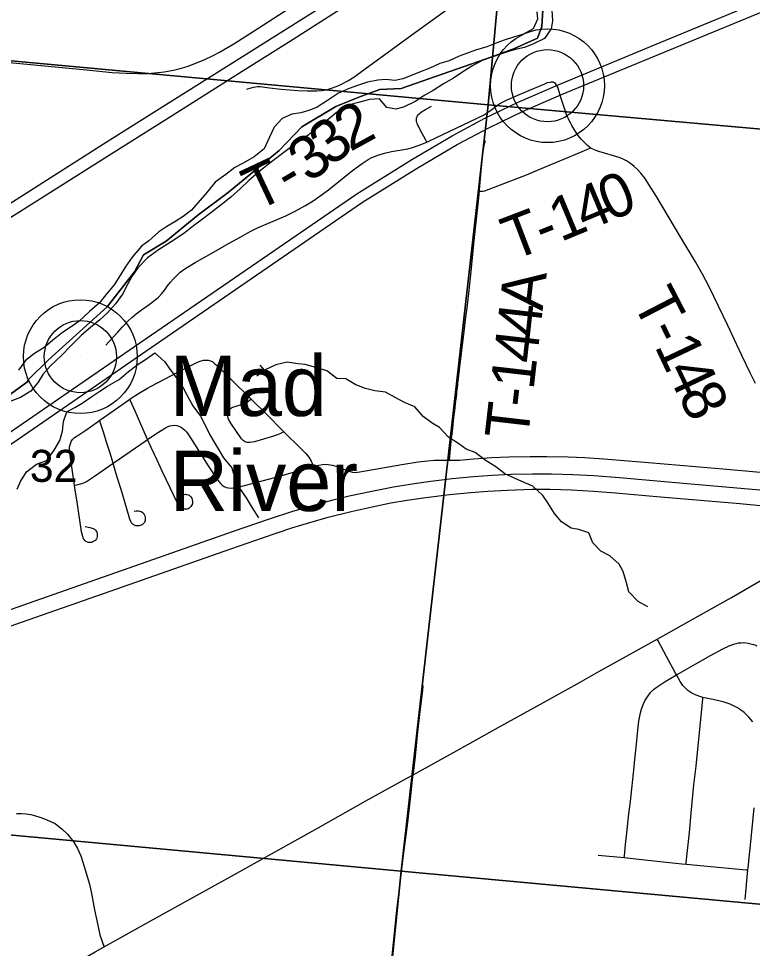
# Model space of a CAD drawing. Extents: x 831 to 1552, y 430 to 870.
# Drawn here: x 1333.77 to 1352.96, y 678.59 to 702.9 of the extents above; entities that cross this region are included whole.
import ezdxf

# ---------------------------------------------------------------- set-up
doc = ezdxf.new("R2010")
doc.units = 0
for name, color, linetype in [('GM_X_Corporation', 7, 'Continuous'), ('GM_X_County_Road', 7, 'Continuous'), ('GM_X_Interstate_Route', 7, 'Continuous'), ('GM_X_Major_River', 7, 'Continuous'), ('GM_X_Minor_River', 7, 'Continuous'), ('GM_X_Rail_Line', 7, 'Continuous'), ('GM_X_Section_Text', 7, 'Continuous'), ('GM_X_State_Route', 7, 'Continuous'), ('GM_X_Township_Road', 7, 'Continuous'), ('GM_X_Township_Road_Text', 7, 'Continuous'), ('GM_X_Unincorporated', 7, 'Continuous'), ('GM_X_Unincorporated_Location', 7, 'Continuous'), ('GM_X_Unincorporated_Text', 7, 'Continuous')]:
    doc.layers.add(name, color=color, linetype=linetype)

msp = doc.modelspace()

# ---------------------------------------------------------------- linework, layer by layer
at = {"layer": 'GM_X_Corporation'}
for points in [[(1327.468, 722.912), (1347.89, 720.702), (1346.049, 700.645), (1325.539, 702.531)], [(1347.89, 720.702), (1366.951, 719.126), (1365.244, 698.931), (1346.049, 700.645)], [(1325.539, 702.531), (1346.049, 700.645), (1343.776, 680.603), (1323.531, 682.478)], [(1346.049, 700.645), (1365.244, 698.931), (1363.462, 678.79), (1343.776, 680.603)], [(1323.531, 682.478), (1343.776, 680.603), (1341.746, 660.547), (1321.979, 662.503), (1321.541, 662.548)], [(1343.776, 680.603), (1363.462, 678.79), (1361.646, 658.883), (1342.018, 660.52), (1341.746, 660.547)]]:
    msp.add_lwpolyline(points, close=True, dxfattribs=at)
for points in [[(1347.533, 704.01), (1347.45, 702.69), (1347.341, 702.388), (1346.735, 702.112), (1346.146, 701.901), (1343.779, 701.073), (1343.216, 701.043), (1342.713, 700.865), (1342.062, 700.599), (1341.175, 700.067), (1340.583, 699.445), (1339.252, 698.351), (1338.453, 697.76), (1337.624, 697.079), (1337.032, 696.725), (1336.796, 696.281), (1336.086, 695.363), (1334.547, 693.974), (1334.014, 693.441), (1334.014, 693.412), (1333.334, 692.909)], [(1333.334, 692.909), (1334.014, 693.412), (1334.014, 693.441), (1334.547, 693.974), (1336.086, 695.363), (1336.796, 696.281), (1337.032, 696.725), (1337.624, 697.079), (1338.453, 697.76), (1339.252, 698.351), (1340.583, 699.445), (1341.175, 700.067), (1342.062, 700.599), (1342.713, 700.865), (1343.216, 701.043), (1343.779, 701.073), (1346.146, 701.901), (1346.735, 702.112), (1347.341, 702.388), (1347.45, 702.69), (1347.533, 704.01)]]:
    msp.add_lwpolyline(points, dxfattribs=at)
at = {"layer": 'GM_X_County_Road'}
for points in [[(1339.741, 701.05), (1339.853, 701.09), (1339.911, 701.105), (1339.969, 701.116), (1340.028, 701.121), (1340.087, 701.121), (1340.146, 701.117), (1340.328, 701.088), (1340.639, 701.052), (1341.072, 701.016), (1341.32, 701.006), (1341.567, 701.01), (1341.689, 701.019), (1341.81, 701.039), (1341.928, 701.072), (1342.103, 701.134), (1342.216, 701.183), (1342.378, 701.271), (1342.534, 701.37), (1342.837, 701.586), (1344.242, 702.614), (1346.358, 704.142)], [(1333.431, 701.759), (1334.174, 701.687), (1335.541, 701.56), (1336.215, 701.491), (1336.586, 701.467), (1336.896, 701.46), (1337.143, 701.465), (1337.328, 701.478), (1337.574, 701.508), (1337.818, 701.553), (1337.998, 701.595), (1338.176, 701.647), (1338.408, 701.732), (1338.637, 701.827), (1338.861, 701.933), (1339.025, 702.019), (1339.399, 702.241), (1340.029, 702.639), (1340.863, 703.18)], [(1350.474, 686.674), (1350.626, 686.759), (1351.385, 687.184), (1352.413, 687.764), (1353.169, 688.195), (1354.196, 688.777), (1354.905, 689.182)], [(1344.092, 683.128), (1345.304, 683.797), (1346.314, 684.361), (1347.422, 684.975), (1348.453, 685.551), (1348.942, 685.823), (1350.474, 686.674)], [(1331.36, 675.855), (1332.212, 676.385), (1332.741, 676.712), (1333.326, 677.065), (1333.915, 677.412), (1334.449, 677.729), (1335.436, 678.305), (1335.775, 678.495), (1337.039, 679.206), (1338.832, 680.197), (1339.319, 680.469), (1341.602, 681.739), (1342.853, 682.441), (1344.04, 683.099), (1344.092, 683.128)]]:
    msp.add_lwpolyline(points, dxfattribs=at)
at = {"layer": 'GM_X_Interstate_Route'}
for points in [[(1331.945, 686.879), (1334.348, 687.724), (1336.811, 688.586), (1339.389, 689.495), (1340.328, 689.819), (1340.919, 690.009), (1341.454, 690.169), (1341.993, 690.315), (1342.415, 690.418), (1342.961, 690.537), (1343.571, 690.654), (1344.06, 690.737), (1344.552, 690.807), (1345.107, 690.872), (1345.663, 690.924), (1346.158, 690.96), (1346.654, 690.983), (1347.213, 690.996), (1347.709, 690.995), (1348.268, 690.98), (1348.81, 690.952), (1349.484, 690.9), (1351.054, 690.763), (1355.364, 690.381)], [(1331.762, 686.388), (1333.874, 687.124), (1336.335, 687.989), (1339.148, 688.976), (1340.145, 689.324), (1340.912, 689.579), (1341.387, 689.725), (1341.866, 689.859), (1342.469, 690.011), (1343.015, 690.135), (1343.502, 690.234), (1343.931, 690.309), (1344.423, 690.379), (1345.041, 690.452), (1345.597, 690.507), (1346.045, 690.543), (1346.558, 690.571), (1347.19, 690.591), (1347.671, 690.591), (1348.231, 690.575), (1348.804, 690.543), (1349.385, 690.495), (1350.561, 690.395), (1352.541, 690.224), (1355.298, 689.97)]]:
    msp.add_lwpolyline(points, dxfattribs=at)
at = {"layer": 'GM_X_Major_River'}
for points in [[(1347.715, 703.116), (1347.732, 702.842), (1347.696, 702.629)], [(1347.326, 703.071), (1347.337, 702.881), (1347.225, 702.632), (1346.978, 702.493), (1346.71, 702.415)], [(1347.696, 702.629), (1347.523, 702.375), (1347.239, 702.236), (1347.001, 702.143), (1346.802, 702.101), (1346.611, 702.045), (1346.396, 701.981), (1346.12, 701.881), (1345.89, 701.802), (1345.621, 701.656), (1345.366, 701.486), (1345.142, 701.339), (1344.88, 701.193), (1344.61, 701.016), (1344.394, 700.892), (1344.139, 700.73), (1343.839, 700.584), (1343.633, 700.528), (1343.398, 700.571), (1343.205, 700.804), (1342.946, 700.779), (1342.655, 700.702), (1342.388, 700.639), (1342.11, 700.463), (1341.87, 700.27), (1341.583, 700.041), (1341.367, 699.871), (1341.142, 699.708), (1340.949, 699.576), (1340.632, 699.347), (1340.307, 699.095), (1340.044, 698.881), (1339.788, 698.666), (1339.562, 698.45), (1339.321, 698.227), (1339.066, 698.027), (1338.795, 697.82), (1338.54, 697.628), (1338.339, 697.481), (1338.122, 697.303), (1337.828, 697.104), (1337.427, 696.854), (1337.141, 696.64), (1336.884, 696.38), (1336.727, 696.155), (1336.623, 695.959), (1336.488, 695.696), (1336.307, 695.441), (1336.089, 695.195), (1335.895, 695.025), (1335.647, 694.817), (1335.414, 694.617), (1335.142, 694.349), (1334.892, 694.088), (1334.605, 693.821), (1334.402, 693.59), (1334.284, 693.395), (1334.088, 693.156), (1333.818, 692.994), (1333.565, 692.893)], [(1346.71, 702.415), (1346.465, 702.337), (1346.273, 702.265), (1346.012, 702.157), (1345.721, 702.072), (1345.484, 701.986), (1345.292, 701.914), (1345.03, 701.79), (1344.786, 701.727), (1344.524, 701.604), (1344.256, 701.496), (1344.064, 701.416), (1343.818, 701.323), (1343.619, 701.281), (1343.361, 701.302), (1343.163, 701.284), (1342.896, 701.237), (1342.635, 701.151), (1342.413, 701.072), (1342.136, 700.949), (1341.851, 700.758), (1341.58, 700.581), (1341.388, 700.502), (1341.151, 700.438), (1340.914, 700.398), (1340.661, 700.289), (1340.45, 700.058), (1340.33, 699.795), (1340.194, 699.493), (1339.931, 699.286), (1339.638, 699.118), (1339.422, 699.001), (1339.19, 698.823), (1338.912, 698.624), (1338.693, 698.355), (1338.521, 698.154), (1338.287, 697.885), (1338.07, 697.722), (1337.854, 697.583), (1337.646, 697.458), (1337.437, 697.326), (1337.174, 697.088), (1336.98, 696.948), (1336.738, 696.664), (1336.557, 696.402), (1336.431, 696.199), (1336.265, 695.937), (1336.054, 695.675), (1335.882, 695.466), (1335.626, 695.236), (1335.354, 694.983), (1335.114, 694.821), (1334.921, 694.689), (1334.658, 694.482), (1334.433, 694.296), (1334.186, 694.142), (1333.946, 693.957), (1333.766, 693.71)]]:
    msp.add_lwpolyline(points, dxfattribs=at)
at = {"layer": 'GM_X_Minor_River'}
for points in [[(1333.728, 690.597), (1333.814, 690.793), (1333.977, 691.05), (1334.237, 691.251), (1334.504, 691.347), (1334.698, 691.61), (1334.845, 691.867), (1334.916, 692.109), (1334.942, 692.367), (1335.029, 692.616), (1335.236, 692.728), (1335.427, 692.839), (1335.687, 693.019), (1335.894, 693.153), (1336.093, 693.287), (1336.399, 693.466), (1336.645, 693.668), (1336.898, 693.862), (1337.09, 693.989), (1337.335, 694.161), (1337.59, 693.922), (1337.725, 693.731), (1337.889, 693.516), (1338.076, 693.24), (1338.18, 693.042), (1338.328, 692.774), (1338.522, 692.506), (1338.671, 692.216), (1338.767, 692.017), (1338.886, 691.826), (1339.013, 691.604), (1339.132, 691.413), (1339.349, 691.152), (1339.422, 690.885), (1339.548, 690.618), (1339.719, 690.365), (1339.876, 690.105), (1340.047, 689.845)], [(1350.229, 687.515), (1349.972, 687.655), (1349.732, 687.908), (1349.667, 688.144), (1349.579, 688.441), (1349.475, 688.632), (1349.235, 688.848), (1349.001, 688.972), (1348.791, 689.195), (1348.68, 689.454), (1348.423, 689.541), (1348.218, 689.574), (1347.969, 689.736), (1347.782, 689.958), (1347.611, 690.241), (1347.477, 690.433), (1347.221, 690.671), (1347.01, 690.757), (1346.76, 690.874), (1346.488, 690.999), (1346.247, 691.176), (1345.976, 691.354), (1345.713, 691.555), (1345.478, 691.641), (1345.282, 691.78), (1345.011, 691.958), (1344.779, 692.204), (1344.583, 692.32), (1344.349, 692.497), (1344.132, 692.743), (1343.86, 692.86), (1343.618, 692.992), (1343.369, 693.132), (1343.089, 693.165), (1342.846, 693.229), (1342.589, 693.323), (1342.325, 693.478), (1342.09, 693.489), (1341.827, 693.689), (1341.539, 693.776), (1341.266, 693.855), (1341.069, 693.873), (1340.789, 693.914), (1340.499, 693.842), (1340.239, 693.723), (1340.002, 693.552)], [(1340.206, 693.699), (1340.089, 693.839)]]:
    msp.add_lwpolyline(points, dxfattribs=at)
at = {"layer": 'GM_X_Rail_Line'}
for points in [[(1331.029, 690.356), (1334.139, 692.492), (1336.804, 694.323), (1342.617, 698.318), (1344.051, 699.217), (1345.113, 699.834), (1345.965, 700.291), (1346.839, 700.712), (1347.861, 701.155), (1350.4, 702.208), (1352.984, 703.272), (1355.322, 704.238), (1357.221, 705.009), (1357.803, 705.212), (1358.348, 705.377), (1359.339, 705.66), (1360.057, 705.898), (1360.633, 706.108), (1361.404, 706.431)], [(1324.617, 685.605), (1327.389, 687.515), (1329.015, 688.636), (1331.181, 690.137), (1334.291, 692.272), (1336.956, 694.104), (1342.764, 698.096), (1344.19, 698.989), (1345.244, 699.602), (1346.087, 700.054), (1346.951, 700.47), (1347.965, 700.91), (1350.503, 701.962), (1353.086, 703.026), (1355.423, 703.992), (1360.057, 705.898)]]:
    msp.add_lwpolyline(points, dxfattribs=at)
at = {"layer": 'GM_X_State_Route'}
for points in [[(1333.187, 697.843), (1335.988, 699.621), (1336.934, 700.218), (1339.247, 701.676), (1342.98, 704.025), (1344.137, 704.754), (1345.24, 705.451), (1347.026, 706.576), (1348.077, 707.238), (1349.128, 707.902), (1350.076, 708.496), (1351.915, 709.656), (1352.545, 710.051), (1352.915, 710.283), (1353.297, 710.524), (1353.703, 710.78), (1354.282, 711.144), (1356.61, 712.615), (1357.165, 712.965)], [(1327.572, 693.951), (1327.781, 694.084), (1329.474, 695.148), (1330.997, 696.104), (1332.731, 697.181), (1334.273, 698.15), (1336.026, 699.258), (1337.813, 700.381), (1339.619, 701.524), (1340.853, 702.296), (1342.496, 703.341), (1344.305, 704.48), (1346.259, 705.713), (1348.062, 706.849), (1349.964, 708.043), (1351.69, 709.137), (1352.765, 709.811)]]:
    msp.add_lwpolyline(points, dxfattribs=at)
at = {"layer": 'GM_X_Township_Road'}
for p, q in [((1348.928, 681.028), (1349.611, 680.96)), ((1352.773, 679.862), (1352.842, 680.637))]:
    msp.add_line(p, q, dxfattribs=at)
for points in [[(1344.45, 699.671), (1344.477, 699.682), (1344.7, 699.785), (1345.926, 700.377), (1346.034, 700.44), (1346.089, 700.474), (1346.14, 700.509), (1346.232, 700.591), (1346.333, 700.658), (1346.44, 700.718), (1346.55, 700.773), (1346.89, 700.923), (1347.532, 701.195), (1347.605, 701.223), (1347.677, 701.239), (1347.707, 701.244), (1347.73, 701.244), (1347.749, 701.238)], [(1348.733, 699.516), (1348.697, 699.54), (1348.646, 699.583), (1348.567, 699.658), (1348.482, 699.749), (1348.403, 699.843), (1348.331, 699.942), (1348.237, 700.102), (1348.209, 700.157), (1348.181, 700.217), (1348.153, 700.273), (1348.129, 700.33), (1348.103, 700.388), (1347.96, 700.808), (1347.91, 700.987), (1347.892, 701.046), (1347.87, 701.102), (1347.842, 701.154), (1347.808, 701.201), (1347.786, 701.218), (1347.749, 701.238)], [(1344.45, 699.671), (1344.41, 699.741), (1344.286, 699.957), (1344.216, 700.099), (1344.203, 700.13), (1344.191, 700.16), (1344.18, 700.202), (1344.175, 700.24), (1344.177, 700.291), (1344.185, 700.324), (1344.198, 700.354), (1344.215, 700.378), (1344.243, 700.409), (1344.308, 700.459), (1344.408, 700.522), (1344.572, 700.611)], [(1345.822, 698.39), (1345.825, 698.419), (1345.867, 698.913), (1345.891, 699.171), (1345.909, 699.361), (1345.925, 699.461), (1345.934, 699.528), (1345.956, 699.621), (1345.981, 699.713)], [(1336.049, 694.356), (1336.223, 694.555), (1336.362, 694.702), (1336.483, 694.836), (1336.638, 694.994), (1336.727, 695.081), (1336.84, 695.18), (1336.984, 695.284), (1337.185, 695.423), (1337.335, 695.535), (1337.431, 695.615), (1337.515, 695.709), (1337.591, 695.808), (1337.663, 695.907), (1337.738, 696.004), (1337.818, 696.097), (1337.905, 696.184), (1337.998, 696.264), (1338.146, 696.374), (1338.389, 696.522), (1338.822, 696.767), (1339.276, 697.024), (1339.483, 697.14), (1339.642, 697.226), (1339.828, 697.332), (1340.021, 697.423), (1340.304, 697.546), (1340.761, 697.741), (1340.984, 697.852), (1341.257, 698.001), (1341.469, 698.131), (1341.623, 698.237), (1341.874, 698.421), (1342.505, 698.924), (1342.753, 699.11), (1342.908, 699.212), (1343.009, 699.267), (1343.057, 699.287), (1343.167, 699.329), (1343.34, 699.379), (1343.522, 699.419), (1343.951, 699.496), (1344.072, 699.528), (1344.248, 699.589), (1344.45, 699.671)], [(1345.822, 698.39), (1345.86, 698.39), (1345.909, 698.39), (1345.96, 698.395), (1346.304, 698.523), (1347.057, 698.814), (1347.568, 699.027), (1348.072, 699.24), (1348.447, 699.396), (1348.692, 699.498), (1348.733, 699.516)], [(1353.041, 693.36), (1352.9, 693.637), (1352.683, 694.088), (1352.551, 694.369), (1352.315, 694.876), (1352.077, 695.383), (1351.833, 695.885), (1351.659, 696.213), (1351.475, 696.537), (1351.091, 697.176), (1350.45, 698.243), (1350.256, 698.56), (1350.153, 698.713), (1350.042, 698.859), (1349.96, 698.95), (1349.869, 699.032), (1349.773, 699.109), (1349.671, 699.176), (1349.617, 699.206), (1349.505, 699.254), (1349.329, 699.311), (1349.095, 699.379), (1348.948, 699.425), (1348.875, 699.45), (1348.833, 699.464), (1348.785, 699.483), (1348.748, 699.505), (1348.733, 699.516)], [(1345.04, 691.356), (1345.064, 691.657), (1345.093, 691.922), (1345.114, 692.105), (1345.136, 692.288), (1345.156, 692.466), (1345.178, 692.649), (1345.208, 692.891), (1345.22, 693.009), (1345.228, 693.066), (1345.234, 693.128), (1345.241, 693.188), (1345.254, 693.31), (1345.261, 693.37), (1345.273, 693.492), (1345.308, 693.797), (1345.427, 694.721), (1345.469, 695.092), (1345.498, 695.339), (1345.542, 695.708), (1345.599, 696.202), (1345.679, 697.005), (1345.731, 697.498), (1345.785, 698.05), (1345.822, 698.39)], [(1336.676, 692.944), (1336.74, 692.99), (1336.947, 693.123), (1337.144, 693.237), (1337.237, 693.288), (1337.935, 693.651), (1338.377, 693.879), (1338.49, 693.932), (1338.548, 693.953), (1338.608, 693.967), (1338.67, 693.97), (1338.73, 693.966), (1338.786, 693.95), (1338.847, 693.921), (1338.905, 693.875), (1338.989, 693.801), (1339.21, 693.583), (1339.339, 693.449), (1339.827, 692.97), (1339.852, 692.945)], [(1335.892, 692.398), (1336.64, 692.917), (1336.676, 692.944)], [(1337.142, 691.891), (1336.938, 692.351), (1336.815, 692.632), (1336.695, 692.902), (1336.676, 692.944)], [(1340.71, 692.095), (1340.672, 692.076), (1340.618, 692.05), (1340.541, 692.016), (1340.409, 691.969), (1339.935, 691.833), (1339.875, 691.819), (1339.813, 691.813), (1339.751, 691.815), (1339.692, 691.831), (1339.641, 691.864), (1339.601, 691.911), (1339.324, 692.32), (1339.26, 692.425), (1339.239, 692.483), (1339.233, 692.544), (1339.244, 692.605), (1339.271, 692.66), (1339.313, 692.705), (1339.366, 692.738), (1339.431, 692.757), (1339.54, 692.789), (1339.632, 692.813), (1339.693, 692.839), (1339.734, 692.864), (1339.811, 692.917), (1339.852, 692.945)], [(1339.852, 692.945), (1340.27, 692.535), (1340.665, 692.14), (1340.71, 692.095)], [(1335.23, 690.695), (1335.196, 690.935), (1335.163, 691.181), (1335.115, 691.487), (1335.107, 691.545), (1335.099, 691.628), (1335.101, 691.686), (1335.109, 691.731), (1335.125, 691.782), (1335.147, 691.84), (1335.181, 691.894), (1335.234, 691.941), (1335.343, 692.019), (1335.524, 692.14), (1335.823, 692.35), (1335.892, 692.398)], [(1336.24, 691.27), (1336.153, 691.558), (1336.078, 691.794), (1335.985, 692.087), (1335.915, 692.321), (1335.892, 692.398)], [(1337.142, 691.891), (1337.334, 692.022), (1337.496, 692.132), (1337.609, 692.2), (1337.667, 692.228), (1337.726, 692.249), (1337.784, 692.263), (1337.843, 692.268), (1337.903, 692.261), (1337.962, 692.243), (1338.017, 692.215), (1338.068, 692.18), (1338.115, 692.139), (1338.156, 692.092), (1338.262, 691.94), (1338.728, 691.204), (1338.935, 690.893), (1339.008, 690.792), (1339.049, 690.746), (1339.094, 690.703), (1339.145, 690.667), (1339.201, 690.641), (1339.261, 690.626), (1339.323, 690.622), (1339.385, 690.625), (1339.508, 690.643), (1340.467, 690.901), (1341.478, 691.189)], [(1340.71, 692.095), (1341.151, 691.66), (1341.279, 691.525), (1341.357, 691.428), (1341.423, 691.324), (1341.451, 691.263), (1341.478, 691.189)], [(1336.24, 691.27), (1336.57, 691.497), (1337.078, 691.847), (1337.142, 691.891)], [(1337.988, 690.431), (1338.019, 690.443), (1338.055, 690.452), (1338.102, 690.458), (1338.135, 690.46), (1338.163, 690.457), (1338.206, 690.444), (1338.227, 690.434), (1338.246, 690.421), (1338.274, 690.395), (1338.301, 690.355), (1338.312, 690.313), (1338.319, 690.27), (1338.315, 690.233), (1338.307, 690.196), (1338.294, 690.166), (1338.272, 690.139), (1338.25, 690.114), (1338.227, 690.097), (1338.203, 690.084), (1338.174, 690.074), (1338.144, 690.068), (1338.112, 690.068), (1338.082, 690.072), (1338.051, 690.084), (1338.026, 690.097), (1337.981, 690.139), (1337.946, 690.19), (1337.915, 690.245), (1337.729, 690.625), (1337.523, 691.068), (1337.392, 691.349), (1337.233, 691.686), (1337.142, 691.891)], [(1345.04, 691.356), (1345.133, 691.353), (1345.215, 691.354), (1345.298, 691.356), (1345.669, 691.386), (1346.145, 691.418), (1346.593, 691.436), (1347.151, 691.45), (1347.585, 691.45), (1348.144, 691.442), (1348.577, 691.425), (1349.072, 691.391), (1350.248, 691.293), (1352.289, 691.116), (1353.463, 691.013)], [(1335.23, 690.695), (1335.29, 690.71), (1335.391, 690.734), (1335.433, 690.743), (1335.491, 690.765), (1335.546, 690.794), (1335.599, 690.826), (1335.752, 690.931), (1335.956, 691.074), (1336.24, 691.27)], [(1336.793, 690.021), (1336.846, 690.025), (1336.908, 690.024), (1336.941, 690.021), (1336.972, 690.01), (1337.002, 689.993), (1337.028, 689.969), (1337.051, 689.936), (1337.067, 689.901), (1337.078, 689.858), (1337.08, 689.831), (1337.079, 689.801), (1337.076, 689.777), (1337.068, 689.749), (1337.059, 689.725), (1337.046, 689.704), (1337.029, 689.686), (1337.013, 689.673), (1336.995, 689.66), (1336.973, 689.65), (1336.949, 689.64), (1336.919, 689.635), (1336.885, 689.632), (1336.864, 689.632), (1336.834, 689.637), (1336.797, 689.652), (1336.761, 689.674), (1336.741, 689.69), (1336.729, 689.706), (1336.714, 689.726), (1336.703, 689.75), (1336.68, 689.814), (1336.479, 690.497), (1336.315, 691.023), (1336.24, 691.27)], [(1341.478, 691.189), (1341.624, 691.226), (1341.72, 691.242), (1341.789, 691.245), (1341.862, 691.241), (1341.922, 691.233), (1341.98, 691.22), (1342.096, 691.184), (1342.267, 691.116), (1342.443, 691.055), (1342.505, 691.04), (1342.57, 691.034), (1342.633, 691.037), (1342.695, 691.045), (1343.791, 691.237), (1344.217, 691.308), (1344.461, 691.338), (1344.645, 691.352), (1344.838, 691.356), (1345.04, 691.356)], [(1335.509, 689.614), (1335.63, 689.594), (1335.69, 689.577), (1335.723, 689.563), (1335.754, 689.546), (1335.779, 689.526), (1335.801, 689.495), (1335.811, 689.469), (1335.821, 689.432), (1335.824, 689.39), (1335.821, 689.351), (1335.813, 689.315), (1335.803, 689.293), (1335.782, 689.265), (1335.765, 689.247), (1335.74, 689.231), (1335.712, 689.217), (1335.676, 689.204), (1335.646, 689.199), (1335.614, 689.198), (1335.585, 689.202), (1335.554, 689.214), (1335.53, 689.228), (1335.501, 689.249), (1335.481, 689.276), (1335.468, 689.299), (1335.446, 689.357), (1335.418, 689.479), (1335.307, 690.199), (1335.239, 690.628), (1335.23, 690.695)], [(1350.976, 685.739), (1350.951, 685.783), (1350.711, 686.22), (1350.498, 686.629), (1350.474, 686.674)], [(1350.976, 685.739), (1351.052, 685.784), (1351.484, 686.028), (1351.862, 686.241), (1352.187, 686.418), (1352.355, 686.498), (1352.473, 686.543), (1352.534, 686.56), (1352.596, 686.573), (1352.66, 686.58), (1352.723, 686.583), (1352.787, 686.579), (1352.85, 686.57), (1352.92, 686.554), (1352.987, 686.535), (1353.048, 686.512), (1353.082, 686.496)], [(1349.611, 680.96), (1349.615, 681.004), (1349.645, 681.304), (1349.677, 681.609), (1349.733, 682.107), (1349.772, 682.43), (1349.866, 683.335), (1349.88, 683.444), (1349.928, 683.923), (1349.963, 684.294), (1349.993, 684.531), (1350.035, 684.746), (1350.065, 684.842), (1350.093, 684.935), (1350.111, 684.984), (1350.148, 685.057), (1350.184, 685.116), (1350.216, 685.166), (1350.256, 685.221), (1350.307, 685.283), (1350.376, 685.357), (1350.473, 685.428), (1350.678, 685.563), (1350.976, 685.739)], [(1351.667, 685.151), (1351.615, 685.164), (1351.49, 685.207), (1351.377, 685.261), (1351.324, 685.293), (1351.273, 685.329), (1351.226, 685.37), (1351.183, 685.414), (1351.144, 685.463), (1351.075, 685.567), (1350.976, 685.739)], [(1344.092, 683.128), (1344.108, 683.235), (1344.148, 683.605), (1344.206, 684.161), (1344.273, 684.779), (1344.338, 685.334), (1344.349, 685.457)], [(1351.23, 680.791), (1351.232, 680.816), (1351.248, 680.994), (1351.314, 681.614), (1351.364, 682.125), (1351.434, 682.863), (1351.487, 683.348), (1351.645, 684.926), (1351.663, 685.109), (1351.667, 685.151)], [(1352.972, 684.512), (1352.924, 684.572), (1352.87, 684.636), (1352.81, 684.698), (1352.744, 684.757), (1352.65, 684.827), (1352.57, 684.879), (1352.469, 684.931), (1352.382, 684.97), (1352.3, 684.998), (1352.219, 685.023), (1352.082, 685.057), (1351.88, 685.1), (1351.751, 685.131), (1351.667, 685.151)], [(1343.225, 675.139), (1343.361, 676.513), (1343.449, 677.378), (1343.506, 678.057), (1343.577, 678.732), (1343.629, 679.237), (1343.66, 679.599), (1343.736, 680.215), (1343.825, 680.955), (1343.945, 681.879), (1344.022, 682.495), (1344.073, 682.99), (1344.092, 683.128)], [(1352.842, 680.637), (1352.847, 680.691), (1352.954, 681.726), (1353.008, 682.264)], [(1333.717, 682.111), (1333.841, 682.111), (1333.964, 682.101), (1334.087, 682.084), (1334.209, 682.057), (1334.327, 682.022), (1334.443, 681.977), (1334.726, 681.849), (1334.912, 681.706), (1335.048, 681.57), (1335.215, 681.363), (1335.305, 681.2), (1335.395, 681.011), (1335.486, 680.731), (1335.621, 680.266), (1335.684, 679.981), (1335.752, 679.598), (1335.838, 679.196), (1335.892, 678.943), (1336.003, 678.623)], [(1349.611, 680.96), (1350.073, 680.914), (1351.115, 680.802), (1351.23, 680.791)], [(1351.23, 680.791), (1352.337, 680.683), (1352.796, 680.641), (1352.842, 680.637)]]:
    msp.add_lwpolyline(points, dxfattribs=at)
at = {"layer": 'GM_X_Unincorporated'}
for centre, radius in [((1347.602, 701.143), 1.488), ((1347.602, 701.143), 0.943), ((1335.384, 694.059), 1.488), ((1335.384, 694.059), 0.943)]:
    msp.add_circle(centre, radius, dxfattribs=at)
at = {"layer": 'GM_X_Unincorporated_Location'}
for p, q in [((1347.602, 701.143), (1347.602, 701.143)), ((1335.384, 694.059), (1335.384, 694.059))]:
    msp.add_line(p, q, dxfattribs=at)

# ---------------------------------------------------------------- texts
at = {"layer": 'GM_X_Section_Text'}
msp.add_text('32', height=0.8371, rotation=0, dxfattribs=at).set_placement((1334.062, 690.785))
at = {"layer": 'GM_X_Township_Road_Text'}
for s, rotation, p in [('2', 28.7131, (1342.438, 699.406)), ('3', 37.6033, (1341.927, 699.008)), ('3', 37.5476, (1341.376, 698.584)), ('T', 25.222, (1339.982, 697.851)), ('-', 30.2569, (1340.845, 698.263)), ('0', 22.7539, (1349.229, 697.588)), ('4', 22.7482, (1348.589, 697.319)), ('1', 22.5123, (1347.943, 697.051)), ('T', 20.9128, (1346.689, 696.564)), ('-', 21.7639, (1347.498, 696.874)), ('A', 83.5872, (1347.473, 695.241)), ('T', 297.3346, (1349.803, 695.503)), ('4', 83.5399, (1347.394, 694.55)), ('-', 295.7342, (1350.189, 694.756)), ('4', 83.4729, (1347.315, 693.859)), ('1', 295.3687, (1350.391, 694.337)), ('1', 83.44, (1347.236, 693.168)), ('4', 295.3965, (1350.691, 693.704)), ('8', 296.4889, (1351.002, 693.051)), ('-', 83.421, (1347.183, 692.708)), ('T', 83.4171, (1347.086, 691.865))]:
    msp.add_text(s, height=1.136, rotation=rotation, dxfattribs=at).set_placement(p)
at = {"layer": 'GM_X_Unincorporated_Text'}
for s, p in [('Mad', (1337.721, 692.508)), ('River', (1337.721, 690.024))]:
    msp.add_text(s, height=1.5795, rotation=0, dxfattribs=at).set_placement(p)

doc.saveas('drawing.dxf')
